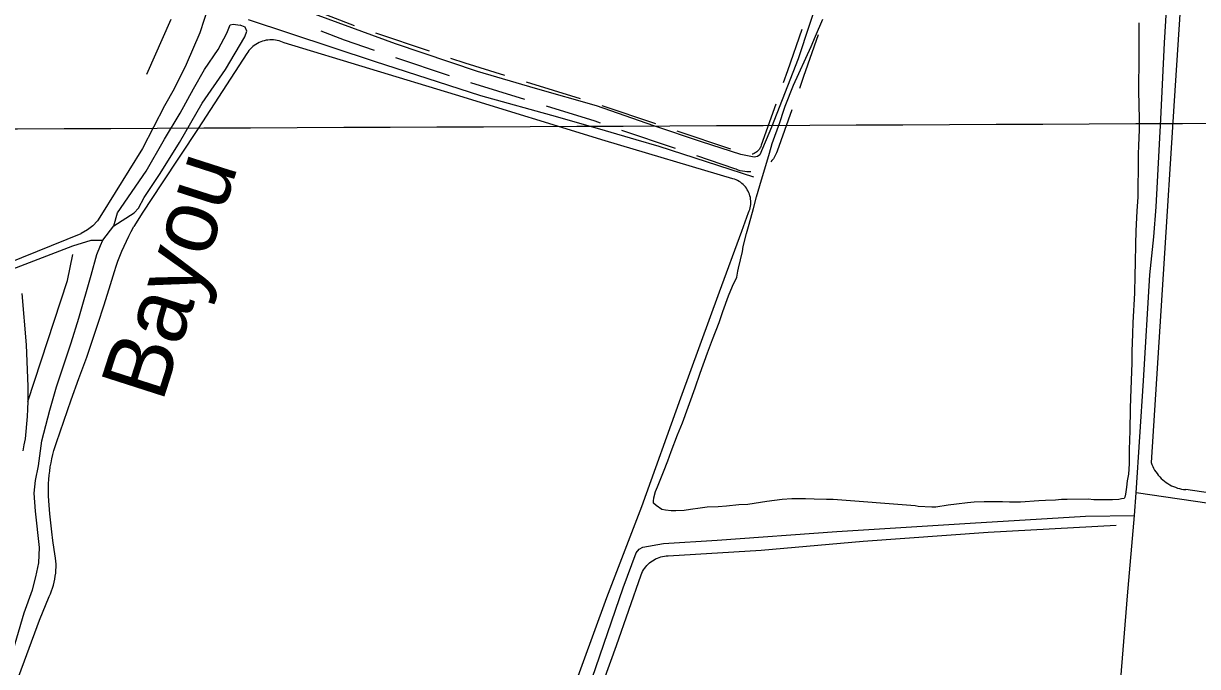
# Model space of a CAD drawing. Extents: x 3419139 to 3457078, y 540382 to 565875.
# Drawn here: x 3447297 to 3449373, y 557047 to 558183 of the extents above; entities that cross this region are included whole.
import ezdxf

# ---------------------------------------------------------------- set-up
doc = ezdxf.new("R2010")
doc.units = 0
for name, color, linetype in [('V-DTCH-CNTR', 7, 'Continuous'), ('V-GRID-MAJR', 7, 'Continuous'), ('V-RIVR-IDEN', 7, 'Continuous'), ('V-ROAD-CNTR', 7, 'Continuous'), ('V-SITE-VEGE', 7, 'Continuous'), ('V-TOPO-SHOR', 7, 'Continuous')]:
    doc.layers.add(name, color=color, linetype=linetype)

msp = doc.modelspace()

# ---------------------------------------------------------------- linework, layer by layer
at = {"layer": 'V-DTCH-CNTR'}
for points in [[(3449348.1, 558298.6), (3449331.4, 558045.7), (3449311.8, 557739.5), (3449290.7, 557407.2), (3449291.9, 557403.7), (3449293.4, 557400.2), (3449295, 557396.9), (3449296.8, 557393.6), (3449298.8, 557390.4), (3449301, 557387.4), (3449303.3, 557384.4), (3449305.8, 557381.6), (3449308.4, 557378.9), (3449311.1, 557376.4), (3449314, 557374), (3449317, 557371.8), (3449320.1, 557369.7), (3449323.4, 557367.8), (3449326.7, 557366.1), (3449330.1, 557364.5), (3449333.6, 557363.2), (3449337.1, 557362), (3449340.7, 557361), (3449344.4, 557360.2), (3449348.1, 557359.6), (3449351.8, 557359.2)], [(3447623.9, 558213.4), (3447608.3, 558166), (3447584.6, 558109.9), (3447562.9, 558067.3), (3447546, 558036.9), (3447507.4, 557961.8), (3447434.9, 557844.9), (3447427.5, 557834), (3447419.3, 557825.3), (3447409.9, 557817.8), (3447398.9, 557811.6)], [(3447514.9, 558093), (3447557.6, 558190.4)], [(3448566.7, 557815.8), (3448578.9, 557848.6), (3448580, 557851.4), (3448581, 557854.2), (3448581.7, 557857.1), (3448582.3, 557860.1), (3448582.7, 557863), (3448582.8, 557866), (3448582.7, 557869), (3448582.5, 557872), (3448582, 557875), (3448581.3, 557877.9), (3448580.4, 557880.8), (3448579.4, 557883.6), (3448578.1, 557886.3), (3448576.6, 557888.9), (3448575, 557891.4), (3448573.2, 557893.8), (3448571.3, 557896.1), (3448569.1, 557898.2), (3448566.9, 557900.2), (3448564.5, 557902), (3448562, 557903.6), (3448559.4, 557905.1), (3448556.7, 557906.3), (3448553.9, 557907.4), (3448551, 557908.3), (3448325.1, 557975.4), (3448060.7, 558056.8), (3447757.8, 558148.3), (3447754.8, 558149.7), (3447751.7, 558150.9), (3447748.6, 558151.9), (3447745.4, 558152.7), (3447742.1, 558153.2), (3447738.9, 558153.6), (3447735.6, 558153.8), (3447732.3, 558153.7), (3447729, 558153.4), (3447725.7, 558152.9), (3447722.5, 558152.2), (3447719.4, 558151.3), (3447716.3, 558150.2), (3447713.2, 558148.9), (3447710.3, 558147.4), (3447707.5, 558145.7), (3447704.8, 558143.9), (3447702.2, 558141.9), (3447699.7, 558139.7), (3447697.4, 558137.3), (3447695.3, 558134.8), (3447693.3, 558132.2), (3447691.5, 558129.4), (3447605.5, 557996.9), (3447540.5, 557899.6), (3447508, 557849.5), (3447491.9, 557823.9)], [(3447284.5, 557018.3), (3447325.3, 557128.7), (3447342.2, 557170.3), (3447344.4, 557175.2), (3447346.4, 557180.2), (3447348.2, 557185.2), (3447349.7, 557190.4), (3447351, 557195.5), (3447352.1, 557200.8), (3447353, 557206.1), (3447353.7, 557211.4), (3447354.1, 557216.7), (3447354.3, 557222.1), (3447354.3, 557227.4), (3447354, 557232.8), (3447353.5, 557238.1), (3447351, 557253.6), (3447348.8, 557269.2), (3447346.7, 557284.8), (3447344.9, 557300.4), (3447343.4, 557316.1), (3447342, 557331.8), (3447340.9, 557347.4), (3447340.7, 557354.9), (3447340.8, 557362.3), (3447341, 557369.7), (3447341.5, 557377.1), (3447342.2, 557384.4), (3447343.1, 557391.8), (3447344.1, 557399.1), (3447345.4, 557406.4), (3447346.9, 557413.7), (3447348.6, 557420.9), (3447350.5, 557428), (3447352.5, 557435.2), (3447354.8, 557442.2), (3447367.9, 557480), (3447381.2, 557517.8), (3447394.8, 557555.4), (3447408.6, 557593), (3447418.8, 557623.1), (3447428.8, 557653.4), (3447438.6, 557683.7), (3447448.2, 557714.1), (3447457.6, 557744.5), (3447460.6, 557753.7), (3447463.8, 557762.7), (3447467.2, 557771.7), (3447470.8, 557780.6), (3447474.6, 557789.5), (3447478.6, 557798.2), (3447482.8, 557806.9), (3447487.3, 557815.4), (3447491.9, 557823.9)], [(3446755.8, 557818.9), (3446759, 557801.6), (3446762.5, 557784.3), (3446766.2, 557767.1), (3446770.1, 557749.9), (3446774.2, 557732.8), (3446778.5, 557715.7), (3446783, 557698.6), (3446787.8, 557681.7), (3446792.7, 557664.8), (3446795.2, 557655.2), (3446798, 557645.7), (3446801, 557636.3), (3446804.2, 557627), (3446807.6, 557617.7), (3446811.3, 557608.5), (3446815.2, 557599.5), (3446904, 557625.2), (3447029.5, 557669.5), (3447215.9, 557738.2), (3447398.9, 557811.6)], [(3448148.5, 556680.9), (3448203.6, 556819.3), (3448263.7, 556992.5), (3448328.1, 557168.4), (3448390.2, 557329.5), (3448458.8, 557521.5), (3448527.1, 557708.8), (3448566.7, 557815.8)], [(3447304.1, 557515), (3447374.5, 557728.5), (3447384.2, 557774.5)], [(3447293.6, 557705.6), (3447301.7, 557614.8), (3447304.3, 557541.2), (3447304.3, 557528), (3447304.1, 557515), (3447303.7, 557501.5), (3447303, 557488.3), (3447302.1, 557475.1), (3447300.9, 557462), (3447299.5, 557448.8), (3447297.4, 557438.2), (3447295.6, 557427.6)], [(3450122.5, 557255.6), (3449956.7, 557281.2), (3449766.5, 557303.5), (3449595.6, 557325.6), (3449427.5, 557348.4), (3449351.8, 557359.2)], [(3448276, 556891.9), (3448345, 557083.5), (3448388.8, 557208.6), (3448390.1, 557211.6), (3448391.5, 557214.5), (3448393.1, 557217.3), (3448394.9, 557220), (3448396.9, 557222.6), (3448399, 557225.1), (3448401.3, 557227.4), (3448403.7, 557229.6), (3448406.2, 557231.7), (3448408.9, 557233.6), (3448411.6, 557235.3), (3448414.5, 557236.8), (3448417.5, 557238.2), (3448420.5, 557239.4), (3448423.6, 557240.4), (3448426.8, 557241.2), (3448430, 557241.8), (3448433.2, 557242.2), (3448436.5, 557242.4), (3448601.2, 557251.9), (3448781.6, 557267.8), (3449002.3, 557283.8), (3449228.9, 557296.3)]]:
    msp.add_lwpolyline(points, dxfattribs=at)
at = {"layer": 'V-GRID-MAJR'}
msp.add_spline([(3423224.7, 557894.1), (3428498.4, 557915.2), (3433772.2, 557937), (3439045.9, 557959.6), (3444319.6, 557983), (3449593.3, 558007.2), (3454867, 558032.1)], degree=3, dxfattribs=at)
at = {"layer": 'V-ROAD-CNTR'}
for p, q in [((3448014.7, 558133.5), (3447920, 558165.7)), ((3448049.7, 558090), (3447955, 558122.1)), ((3448183.3, 558048.2), (3448087.7, 558077.6)), ((3448281.6, 558049.2), (3448186.1, 558078.7)), ((3448414.6, 558005.2), (3448319.8, 558037.3)), ((3448449.6, 557961.7), (3448354.9, 557993.8)), ((3448547.2, 557960.3), (3448452.4, 557992.4))]:
    msp.add_line(p, q, dxfattribs=at)
for points in [[(3447882.1, 558178.6), (3447874.4, 558181.2), (3447788.8, 558214.6)], [(3447917.1, 558135), (3447864.1, 558153), (3447823.1, 558169)], [(3448673.2, 558171.9), (3448647.8, 558099.1), (3448640.1, 558077.5)], [(3448701.7, 558162.3), (3448676.1, 558089.2), (3448668.6, 558067.9)], [(3448147.9, 558090.5), (3448077.4, 558112.2), (3448052.5, 558120.7)], [(3448317, 558006.6), (3448307.6, 558009.8), (3448221.5, 558036.4)], [(3448626.8, 558039.8), (3448601.1, 557967.4), (3448600.3, 557965.3), (3448599.6, 557963.7), (3448598.8, 557962.2), (3448597.9, 557960.8), (3448596.8, 557959.4), (3448595.7, 557958.1), (3448594.5, 557956.9), (3448593.2, 557955.8), (3448591.8, 557954.7), (3448590.4, 557953.8), (3448588.9, 557953), (3448587.3, 557952.3), (3448585.7, 557951.7), (3448585.4, 557951.6)], [(3448655.2, 558030.2), (3448629.3, 557957.2), (3448628.1, 557954), (3448626.5, 557950.4), (3448624.7, 557947), (3448622.6, 557943.7), (3448620.2, 557940.6), (3448617.9, 557937.9)], [(3448582.8, 557920.7), (3448579.6, 557920.6), (3448575.8, 557920.6), (3448571.9, 557920.9), (3448568, 557921.6), (3448564.2, 557922.4), (3448560.5, 557923.6), (3448556.9, 557925), (3448554.7, 557926.1), (3448487.5, 557948.9)]]:
    msp.add_lwpolyline(points, dxfattribs=at)
at = {"layer": 'V-SITE-VEGE'}
for points in [[(3448873.1, 557330.5), (3448728.3, 557341.6), (3448716.7, 557341.6), (3448695, 557342.3), (3448679.7, 557343), (3448655.4, 557342.9), (3448638.2, 557341.7), (3448611.2, 557337.9), (3448577.6, 557332.9), (3448561.5, 557332.1), (3448539.8, 557329.8), (3448525.2, 557328.6), (3448505.4, 557328.2), (3448493.1, 557326.3), (3448475.9, 557324.3), (3448465, 557322), (3448450.4, 557321.6), (3448442.2, 557321.6), (3448432.1, 557322.7), (3448425.7, 557324.2), (3448415.6, 557330.9), (3448410.7, 557335.3), (3448410.7, 557338.7), (3448411.4, 557344.7), (3448414.4, 557355.9), (3448417.7, 557363.8), (3448428.1, 557390.8), (3448435.9, 557410.2), (3448442.2, 557426.3), (3448453.4, 557455.9), (3448461.9, 557477.3), (3448484.1, 557539.1), (3448493, 557564.6), (3448506.4, 557600.9), (3448515.3, 557624.5), (3448526.8, 557654.5), (3448533.1, 557673.6), (3448543.1, 557701.3), (3448550.5, 557718.5), (3448558.3, 557734.6), (3448559.8, 557745.1), (3448560.9, 557750.3), (3448567.9, 557779.9), (3448569.3, 557788.5), (3448574.9, 557811.7), (3448579.7, 557828.2), (3448587.5, 557855.5), (3448592.6, 557876.5), (3448601.9, 557906.1), (3448607.4, 557925.6), (3448615.9, 557953.3), (3448620.4, 557970.5), (3448634.1, 558007.6), (3448641.1, 558029.3), (3448643.7, 558036.8), (3448658.2, 558073.5), (3448689.4, 558142.1), (3448697.2, 558160.4), (3448710.2, 558190)], [(3449268.7, 558183.6), (3449269, 558111.8), (3449268.3, 558075.5), (3449268.4, 558063.6), (3449269.3, 558013.8), (3449269.4, 557993.2), (3449268.7, 557983.1), (3449268.7, 557979.8), (3449268, 557967.8), (3449267.6, 557951.3), (3449267.7, 557921), (3449267.1, 557898.6), (3449266.8, 557875.8), (3449265.3, 557851.8), (3449263.6, 557815.9), (3449262.9, 557792.7), (3449262.3, 557759.8), (3449262, 557737.7), (3449261, 557705.9), (3449258.5, 557654.6), (3449257.8, 557634.4), (3449256.4, 557603), (3449256.5, 557583.2), (3449254.1, 557520.7), (3449253.8, 557502.7), (3449252.8, 557463.1), (3449251.8, 557430.1), (3449251.5, 557413.3), (3449251.5, 557404.7), (3449250.4, 557386.7), (3449248.2, 557374.8), (3449246.8, 557363.5), (3449245.3, 557351.2), (3449244.2, 557345.9), (3449242.7, 557343.7), (3449238.2, 557342.9), (3449233.7, 557341.8), (3449222.5, 557341), (3449189.2, 557340.9), (3449179.1, 557342), (3449142.1, 557341.9), (3449132.4, 557341.5), (3449121.5, 557340.7), (3449103.9, 557339.9), (3449092.3, 557339.1), (3449059.4, 557337.1), (3449040.3, 557337), (3449027.6, 557337.4), (3449008.2, 557337.7), (3448995.4, 557337.6), (3448977.5, 557337.2), (3448965.9, 557336), (3448946.4, 557333.7), (3448931.5, 557331.8), (3448909.8, 557328.4), (3448903.1, 557328), (3448878.7, 557329.4), (3448873.1, 557330.5)]]:
    msp.add_lwpolyline(points, dxfattribs=at)
at = {"layer": 'V-TOPO-SHOR'}
for q in [(3447492.2, 557848.3), (3447463.2, 557848.3)]:
    msp.add_line((3447456.2, 557825), q, dxfattribs=at)
for points in [[(3449295.6, 557805.7), (3449299.7, 557858.4), (3449308, 558013.3), (3449314.1, 558148.6), (3449319.6, 558236.5), (3449330.6, 558401.5), (3449338.1, 558494.2), (3449345.6, 558597), (3449356.5, 558738.3), (3449357.9, 558844.5), (3449360.7, 558900), (3449368.2, 558981.8), (3449371.6, 559062.3), (3449379.8, 559161.8), (3449388.7, 559303.8), (3449396.9, 559428.2), (3449401.7, 559499.3), (3449407.1, 559564.9), (3449409.9, 559643.3), (3449413.3, 559673.1), (3449422.8, 559717.7), (3449436.4, 559752.2)], [(3448707.2, 558244), (3448666.5, 558120.2), (3448619.1, 557999.2), (3448598.7, 557950.5), (3448594.7, 557947.8), (3448588.6, 557946.5), (3448564.9, 557951.2), (3448495.3, 557973.6), (3448411.4, 558002), (3448310, 558037.3), (3448201.8, 558067.8), (3448099.7, 558097.6), (3447954.3, 558146.4), (3447775.7, 558212.2)], [(3447463.2, 557848.3), (3447513.4, 557921.9), (3447545.9, 557978), (3447573.7, 558024), (3447597.4, 558067.3), (3447617, 558101.1), (3447640.7, 558136.9), (3447656.3, 558165.3), (3447662.4, 558180.2), (3447667.2, 558181.5), (3447680, 558179.5)], [(3447492.2, 557848.3), (3447499.9, 557856.3), (3447510, 557875.2), (3447538.5, 557917.8), (3447572.3, 557972.6), (3447612.9, 558041.6), (3447654.2, 558101.1), (3447688.1, 558159.2), (3447691.5, 558169.3), (3447688.8, 558176.1), (3447680, 558179.5)], [(3448588.2, 557911), (3448420.5, 557965.2), (3448379.9, 557976.8), (3448325.8, 557993), (3448241.3, 558016.8), (3448105.4, 558054.7), (3447917.4, 558115.7), (3447694.8, 558188.9)], [(3447261.9, 557018.8), (3447297.9, 557141.7), (3447312.4, 557182.1), (3447318.7, 557205.1), (3447324.1, 557229.6), (3447325.2, 557256.9), (3447317.9, 557321), (3447315.4, 557352.7), (3447318.1, 557375.3), (3447323.2, 557401), (3447329, 557445.4), (3447343.4, 557499.3), (3447355.2, 557540.9), (3447381.1, 557618.5), (3447394.8, 557662.1), (3447416.3, 557737.8), (3447426.5, 557774.3), (3447432.7, 557790.5), (3447437.1, 557799.6), (3447456.2, 557825)], [(3449092.9, 554806.9), (3449105.7, 555023.1), (3449120.8, 555245.6), (3449133.5, 555451.1), (3449147.1, 555667.3), (3449161.4, 555890.2), (3449171.5, 556052.1), (3449183.2, 556239), (3449199.8, 556471.4), (3449211.8, 556684.4), (3449223.9, 556847.6), (3449236.1, 557010.3), (3449248.6, 557171.5), (3449261.2, 557313.6), (3449264.2, 557353.2), (3449277, 557551.2), (3449288.3, 557738.8), (3449295.6, 557805.7)], [(3446785.9, 557561.6), (3446812.4, 557571.8), (3447015.2, 557649.8), (3447245.7, 557736.9), (3447383.7, 557790), (3447416.5, 557800), (3447437.1, 557799.6)], [(3450127.6, 557239.7), (3449876.1, 557270.5), (3449647.6, 557301), (3449417.1, 557331.1), (3449264.2, 557353.2)], [(3448523.2, 557269.7), (3448734.8, 557285.2), (3448970.6, 557300.1), (3449174.4, 557312.1), (3449261.2, 557313.6)], [(3448179.8, 556682.6), (3448243.8, 556859.8), (3448302.2, 557025.8), (3448357.1, 557185.9), (3448379.8, 557247.4), (3448385.4, 557253.7), (3448391.7, 557257.7), (3448428.1, 557264.1), (3448523.2, 557269.7)]]:
    msp.add_lwpolyline(points, dxfattribs=at)

# ---------------------------------------------------------------- texts
at = {"layer": 'V-RIVR-IDEN'}
msp.add_text('Bayou', height=116, rotation=72.204, dxfattribs=at).set_placement((3447542, 557511.5))

doc.saveas('drawing.dxf')
